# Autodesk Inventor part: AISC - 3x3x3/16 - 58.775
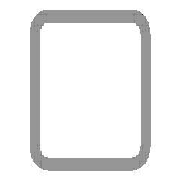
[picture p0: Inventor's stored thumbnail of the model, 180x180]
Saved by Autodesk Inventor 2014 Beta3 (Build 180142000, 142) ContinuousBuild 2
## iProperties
IsCustomPart: 1
_CCFamilyMember: 9
_CCFamilyDisplayName: ANSI AISC (Square) - Tube
_FrameMemberDoc: Frame Member File
_Version: 15.0.0
_GetPNFromCC: 1
Created: 2011-01
Part Number: AISC - 3x3x3/16 - 58.775
Material: Steel, Mild
Description: Tube
Document SubType Name: Modeling
Standard: ANSI
Designer: Beta-8540w
Standards Organization: ANSI
Language: en-US
Size Designation: 3x3x3/16
Categories: <MemberInstance><Categories><Category DisplayName="Structural Shapes" InternalName="089c4875-fa83-4c05-b084-43b9cc11f5ed" Mnemonic="GRDR"><CategoryParameter Dis
Stock Number: 3x3x3/16
Density: 7.86 g/cm^3
Appearance: Steel
G_L: 58.775 in
G_W: 3.000 in
G_H: 3.000 in
+AE3CA65D-4403-45DE-BD14-7280831DFD21+CUTDETAIL1: Cut
Author: Beta-8540w
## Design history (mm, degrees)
node "Start plane"
node "End plane"
sketch "Sketch"
  geometry: L1 (-38.1, -28.575)-(-38.1, 28.575); L2 (-28.575, 38.1)-(28.575, 38.1); L3 (38.1, 28.575)-(38.1, -28.575); L4 (28.575, -38.1)-(-28.575, -38.1); L5 (-28.575, 33.337)-(28.575, 33.338); L6 (33.338, 28.575)-(33.338, -28.575); L7 (28.575, -33.337)-(-28.575, -33.338); L8 (-33.338, -28.575)-(-33.338, 28.575); L9 (0, 56.102)-(0, -56.102) reference; L10 (-56.102, 0)-(56.102, 0) reference; A1 r 9.525 centre (-28.575, -28.575) between (-38.1, -28.575) and (-28.575, -38.1); A2 r 9.525 centre (-28.575, 28.575) between (-28.575, 38.1) and (-38.1, 28.575); A3 r 9.525 centre (28.575, 28.575) between (38.1, 28.575) and (28.575, 38.1); A4 r 9.525 centre (28.575, -28.575) between (28.575, -38.1) and (38.1, -28.575); A5 r 4.763 centre (-28.575, 28.575) between (-28.575, 33.337) and (-33.338, 28.575); A6 r 4.763 centre (28.575, 28.575) between (33.338, 28.575) and (28.575, 33.338); A7 r 4.763 centre (28.575, -28.575) between (28.575, -33.337) and (33.338, -28.575); A8 r 4.763 centre (-28.575, -28.575) between (-33.338, -28.575) and (-28.575, -33.338)
  constraints: 16 end point, 16 point on circle, 8 centre point, 8 tangent, 4 parallel, 3 equal radius, 2 perpendicular, 7 other
  dimensions: "d10" = 76.2 distance between parallel lines of L2 L4 (= G_H); "d11" = 76.2 distance between parallel lines of L1 L3 (= G_W); "d12" = 4.7625 distance between parallel lines of L3 L6 (= G_T); "d15" = 38.1 distance between parallel lines of L2 L10 (= 0.5 x d10); "d16" = 38.1 distance between parallel lines of L9 L3 (= 0.5 x d11); "d17" = 9.525 radius of A1 (= G_IR)
extrude "Body" new body sketch "Sketch" stored distance "d3" = 1492.89148 (= G_L); taper "d4" = 0 deg
node "Driven Length"
  sketch "Sketch3"
    geometry: L1 (0, 0)-(10, 0) reference
    constraints: 2 end point, 1 horizontal
  workplane "Work Plane3"
  sketch "Sketch4"
    geometry: L1 (-2, 0)-(12, 0) reference; L2 (-2, 1492.891)-(12, 1492.891) reference
    dimensions: "d19" = 1492.89148 distance between parallel lines of L1 L2 (derived)
workplane "Work Plane4"
split "Split1"
body "Solid1"
other parameters: "G_W" = 76.2 [user parameter; used in 1 equation term], "G_H" = 76.2 [user parameter; used in 1 equation term], "G_T" = 4.7625 [user parameter; used in 1 equation term], "G_IR" = 9.525 [user parameter; used in 1 equation term], "G_L" = 1492.89148 (= d19) [user parameter; used in 1 equation term], "G_OFFSET_START" = 0 [user parameter; used in 1 equation term], "G_OFFSET_END" = -31.10852 [user parameter; used in 1 equation term], "d13" = 0 (computed from G_OFFSET_START), "d14" = 1492.89148 (= G_OFFSET_END + B_L), "B_L" = 1524 [user parameter; used in 1 equation term], "d18" = 90 deg
